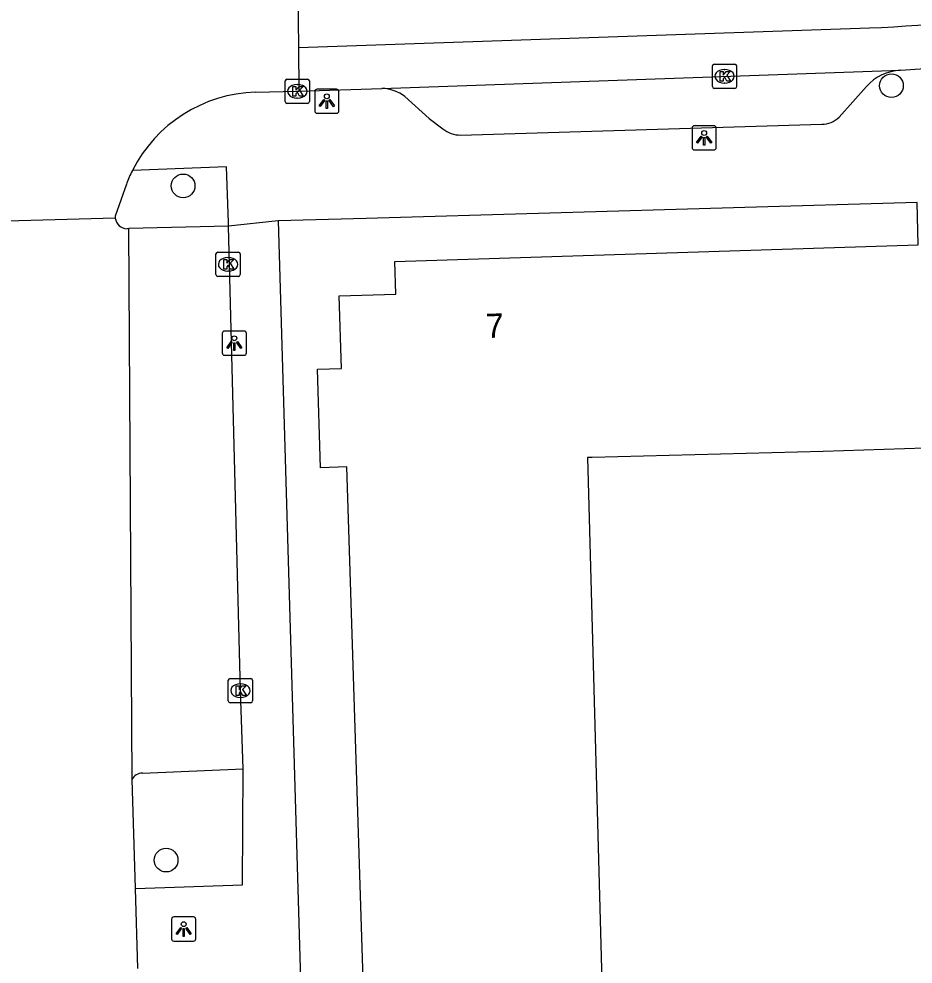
# Model space of a CAD drawing. Extents: x 162250 to 162654, y 380744 to 381605.
# Drawn here: x 162462.41 to 162499.28, y 381169.06 to 381208.05 of the extents above; entities that cross this region are included whole.
import ezdxf

# ---------------------------------------------------------------- set-up
doc = ezdxf.new("R2010")
doc.units = 0
for name, color, linetype in [('IMGEO_Boom', 7, 'Continuous'), ('IMGEO_Kolk', 7, 'Continuous'), ('IMGEO_Lichtpunt', 7, 'Continuous'), ('IMGEO_Pand', 7, 'Continuous'), ('IMGEO_Pand_nummerreeks', 7, 'Continuous'), ('IMGEO_Parkeervlak_open', 7, 'Continuous'), ('IMGEO_Rijbaan_lokaal_gesloten', 7, 'Continuous'), ('IMGEO_Voetpad_open', 7, 'Continuous'), ('IMGEO_Woonerf_open', 7, 'Continuous')]:
    doc.layers.add(name, color=color, linetype=linetype)

msp = doc.modelspace()

# ---------------------------------------------------------------- linework, layer by layer
at = {"layer": 'IMGEO_Boom'}
for centre in [(162498.385, 381205.295), (162469.18, 381201.161), (162468.48, 381173.35)]:
    msp.add_circle(centre, 0.489, dxfattribs=at)
at = {"layer": 'IMGEO_Kolk'}
for p, q in [((162491.003, 381205.258), (162491.003, 381206.11)), ((162491.078, 381206.184), (162491.93, 381206.184)), ((162492.004, 381206.11), (162492.004, 381205.258)), ((162491.491, 381205.964), (162491.516, 381205.964)), ((162473.389, 381204.639), (162473.389, 381205.491)), ((162473.464, 381205.565), (162474.316, 381205.565)), ((162473.877, 381205.345), (162473.902, 381205.345)), ((162474.39, 381205.491), (162474.39, 381204.639)), ((162491.514, 381205.404), (162491.489, 381205.404)), ((162491.93, 381205.184), (162491.078, 381205.184)), ((162474.316, 381204.565), (162473.464, 381204.565)), ((162473.9, 381204.785), (162473.875, 381204.785)), ((162470.534, 381197.501), (162470.534, 381198.353)), ((162470.609, 381198.427), (162471.461, 381198.427)), ((162471.535, 381198.353), (162471.535, 381197.501)), ((162471.022, 381198.207), (162471.047, 381198.207)), ((162471.045, 381197.647), (162471.02, 381197.647)), ((162471.461, 381197.427), (162470.609, 381197.427)), ((162471.044, 381179.916), (162471.044, 381180.768)), ((162471.119, 381180.842), (162471.971, 381180.842)), ((162472.045, 381180.768), (162472.045, 381179.916)), ((162471.532, 381180.622), (162471.557, 381180.622)), ((162471.555, 381180.062), (162471.53, 381180.062)), ((162471.971, 381179.842), (162471.119, 381179.842))]:
    msp.add_line(p, q, dxfattribs=at)
for points in [[(162491.003, 381205.258), (162491.003, 381206.11)], [(162491.078, 381206.184), (162491.93, 381206.184)], [(162492.004, 381206.11), (162492.004, 381205.258)], [(162491.324, 381205.884), (162491.447, 381205.884), (162491.447, 381205.733), (162491.577, 381205.884), (162491.741, 381205.884), (162491.595, 381205.733), (162491.748, 381205.484), (162491.596, 381205.484), (162491.511, 381205.648), (162491.447, 381205.581), (162491.447, 381205.484), (162491.324, 381205.484), (162491.324, 381205.884)], [(162473.389, 381204.639), (162473.389, 381205.491)], [(162473.464, 381205.565), (162474.316, 381205.565)], [(162474.39, 381205.491), (162474.39, 381204.639)], [(162473.71, 381205.265), (162473.833, 381205.265), (162473.833, 381205.114), (162473.963, 381205.265), (162474.127, 381205.265), (162473.981, 381205.114), (162474.134, 381204.865), (162473.982, 381204.865), (162473.897, 381205.029), (162473.833, 381204.962), (162473.833, 381204.865), (162473.71, 381204.865), (162473.71, 381205.265)], [(162491.93, 381205.184), (162491.078, 381205.184)], [(162474.316, 381204.565), (162473.464, 381204.565)], [(162470.534, 381197.501), (162470.534, 381198.353)], [(162470.609, 381198.427), (162471.461, 381198.427)], [(162471.535, 381198.353), (162471.535, 381197.501)], [(162470.855, 381198.127), (162470.978, 381198.127), (162470.978, 381197.976), (162471.108, 381198.127), (162471.272, 381198.127), (162471.126, 381197.976), (162471.279, 381197.727), (162471.127, 381197.727), (162471.042, 381197.891), (162470.978, 381197.824), (162470.978, 381197.727), (162470.855, 381197.727), (162470.855, 381198.127)], [(162471.461, 381197.427), (162470.609, 381197.427)], [(162471.044, 381179.916), (162471.044, 381180.768)], [(162471.119, 381180.842), (162471.971, 381180.842)], [(162472.045, 381180.768), (162472.045, 381179.916)], [(162471.365, 381180.542), (162471.488, 381180.542), (162471.488, 381180.391), (162471.618, 381180.542), (162471.782, 381180.542), (162471.636, 381180.391), (162471.789, 381180.142), (162471.637, 381180.142), (162471.552, 381180.306), (162471.488, 381180.239), (162471.488, 381180.142), (162471.365, 381180.142), (162471.365, 381180.542)], [(162471.971, 381179.842), (162471.119, 381179.842)]]:
    msp.add_lwpolyline(points, dxfattribs=at)
for centre, start, end in [((162491.08, 381206.108), 91.552, 178.448), ((162491.08, 381206.108), 91.552, 178.448), ((162491.928, 381206.108), 1.552, 88.448), ((162491.928, 381206.108), 1.552, 88.448), ((162473.466, 381205.489), 91.552, 178.448), ((162473.466, 381205.489), 91.552, 178.448), ((162474.314, 381205.489), 1.552, 88.448), ((162474.314, 381205.489), 1.552, 88.448), ((162491.08, 381205.26), 181.552, 268.448), ((162491.08, 381205.26), 181.552, 268.448), ((162491.928, 381205.26), 271.552, 358.448), ((162491.928, 381205.26), 271.552, 358.448), ((162473.466, 381204.641), 181.552, 268.448), ((162473.466, 381204.641), 181.552, 268.448), ((162474.314, 381204.641), 271.552, 358.448), ((162474.314, 381204.641), 271.552, 358.448), ((162470.611, 381198.351), 91.552, 178.448), ((162470.611, 381198.351), 91.552, 178.448), ((162471.459, 381198.351), 1.552, 88.448), ((162471.459, 381198.351), 1.552, 88.448), ((162470.611, 381197.503), 181.552, 268.448), ((162470.611, 381197.503), 181.552, 268.448), ((162471.459, 381197.503), 271.552, 358.448), ((162471.459, 381197.503), 271.552, 358.448), ((162471.121, 381180.766), 91.552, 178.448), ((162471.121, 381180.766), 91.552, 178.448), ((162471.969, 381180.766), 1.552, 88.448), ((162471.969, 381180.766), 1.552, 88.448), ((162471.121, 381179.918), 181.552, 268.448), ((162471.121, 381179.918), 181.552, 268.448), ((162471.969, 381179.918), 271.552, 358.448), ((162471.969, 381179.918), 271.552, 358.448)]:
    msp.add_arc(centre, 0.0765, start, end, dxfattribs=at)
for centre, major_axis, ratio, start_param, end_param in [((162491.49, 381205.684), (-0.387, 0.002), 0.722429, 4.712389, 7.853982), ((162491.515, 381205.684), (-0.39, 0.002), 0.717154, 1.570796, 4.712389), ((162473.876, 381205.065), (-0.387, 0.002), 0.722429, 4.712389, 7.853982), ((162473.901, 381205.065), (-0.39, 0.002), 0.717154, 1.570796, 4.712389), ((162471.021, 381197.927), (-0.387, 0.002), 0.722429, 4.712389, 7.853982), ((162471.046, 381197.927), (-0.39, 0.002), 0.717154, 1.570796, 4.712389), ((162471.531, 381180.342), (-0.387, 0.002), 0.722429, 4.712389, 7.853982), ((162471.556, 381180.342), (-0.39, 0.002), 0.717154, 1.570796, 4.712389)]:
    msp.add_ellipse(centre, major_axis=major_axis, ratio=ratio, start_param=start_param, end_param=end_param, dxfattribs=at)
at = {"layer": 'IMGEO_Lichtpunt'}
for p, q in [((162474.61, 381205.057), (162474.61, 381204.25)), ((162474.61, 381205.057), (162474.61, 381204.25)), ((162475.512, 381205.152), (162474.704, 381205.152)), ((162475.512, 381205.152), (162474.704, 381205.152)), ((162475.606, 381204.25), (162475.606, 381205.057)), ((162475.606, 381204.25), (162475.606, 381205.057)), ((162474.704, 381204.156), (162475.512, 381204.156)), ((162474.704, 381204.156), (162475.512, 381204.156)), ((162490.166, 381203.546), (162490.166, 381202.739)), ((162490.166, 381203.546), (162490.166, 381202.739)), ((162491.068, 381203.641), (162490.26, 381203.641)), ((162491.068, 381203.641), (162490.26, 381203.641)), ((162491.162, 381202.739), (162491.162, 381203.546)), ((162491.162, 381202.739), (162491.162, 381203.546)), ((162490.26, 381202.645), (162491.068, 381202.645)), ((162490.26, 381202.645), (162491.068, 381202.645)), ((162471.696, 381195.174), (162470.888, 381195.174)), ((162471.696, 381195.174), (162470.888, 381195.174)), ((162470.794, 381195.079), (162470.794, 381194.272)), ((162470.794, 381195.079), (162470.794, 381194.272)), ((162471.79, 381194.272), (162471.79, 381195.079)), ((162471.79, 381194.272), (162471.79, 381195.079)), ((162470.888, 381194.178), (162471.696, 381194.178)), ((162470.888, 381194.178), (162471.696, 381194.178)), ((162469.609, 381171.007), (162468.801, 381171.007)), ((162469.609, 381171.007), (162468.801, 381171.007)), ((162468.707, 381170.912), (162468.707, 381170.105)), ((162468.707, 381170.912), (162468.707, 381170.105)), ((162469.703, 381170.105), (162469.703, 381170.912)), ((162469.703, 381170.105), (162469.703, 381170.912)), ((162468.801, 381170.011), (162469.609, 381170.011)), ((162468.801, 381170.011), (162469.609, 381170.011))]:
    msp.add_line(p, q, dxfattribs=at)
for points in [[(162474.984, 381204.721), (162475.023, 381204.693), (162474.835, 381204.431), (162474.797, 381204.458), (162474.984, 381204.721)], [(162475.086, 381204.673), (162475.133, 381204.673), (162475.133, 381204.351), (162475.086, 381204.351), (162475.086, 381204.673)], [(162475.196, 381204.693), (162475.234, 381204.72), (162475.421, 381204.458), (162475.382, 381204.43), (162475.196, 381204.693)], [(162490.54, 381203.21), (162490.579, 381203.182), (162490.391, 381202.92), (162490.353, 381202.947), (162490.54, 381203.21)], [(162490.642, 381203.162), (162490.689, 381203.162), (162490.689, 381202.84), (162490.642, 381202.84), (162490.642, 381203.162)], [(162490.752, 381203.182), (162490.79, 381203.209), (162490.977, 381202.947), (162490.938, 381202.919), (162490.752, 381203.182)], [(162471.168, 381194.743), (162471.207, 381194.715), (162471.019, 381194.453), (162470.981, 381194.48), (162471.168, 381194.743)], [(162471.38, 381194.715), (162471.418, 381194.742), (162471.605, 381194.48), (162471.566, 381194.452), (162471.38, 381194.715)], [(162471.27, 381194.695), (162471.317, 381194.695), (162471.317, 381194.373), (162471.27, 381194.373), (162471.27, 381194.695)], [(162469.081, 381170.576), (162469.12, 381170.548), (162468.932, 381170.286), (162468.894, 381170.313), (162469.081, 381170.576)], [(162469.293, 381170.548), (162469.331, 381170.575), (162469.518, 381170.313), (162469.479, 381170.285), (162469.293, 381170.548)], [(162469.183, 381170.528), (162469.23, 381170.528), (162469.23, 381170.206), (162469.183, 381170.206), (162469.183, 381170.528)]]:
    msp.add_lwpolyline(points, dxfattribs=at)
for centre in [(162475.109, 381204.855), (162490.665, 381203.344), (162471.293, 381194.877), (162469.206, 381170.71)]:
    msp.add_circle(centre, 0.0994, dxfattribs=at)
for centre, start, end in [((162474.704, 381205.057), 90, 180), ((162474.704, 381205.057), 90, 180), ((162475.512, 381205.057), 0, 90), ((162475.512, 381205.057), 0, 90), ((162474.704, 381204.25), 180, 270), ((162474.704, 381204.25), 180, 270), ((162475.512, 381204.25), 270, 0), ((162475.512, 381204.25), 270, 360), ((162490.26, 381203.546), 90, 180), ((162490.26, 381203.546), 90, 180), ((162491.068, 381203.546), 0, 90), ((162491.068, 381203.546), 0, 90), ((162490.26, 381202.739), 180, 270), ((162490.26, 381202.739), 180, 270), ((162491.068, 381202.739), 270, 0), ((162491.068, 381202.739), 270, 360), ((162470.888, 381195.079), 90, 180), ((162470.888, 381195.079), 90, 180), ((162471.696, 381195.079), 0, 90), ((162471.696, 381195.079), 0, 90), ((162470.888, 381194.272), 180, 270), ((162470.888, 381194.272), 180, 270), ((162471.696, 381194.272), 270, 0), ((162471.696, 381194.272), 270, 360), ((162468.801, 381170.912), 90, 180), ((162468.801, 381170.912), 90, 180), ((162469.609, 381170.912), 0, 90), ((162469.609, 381170.912), 0, 90), ((162468.801, 381170.105), 180, 270), ((162468.801, 381170.105), 180, 270), ((162469.609, 381170.105), 270, 0), ((162469.609, 381170.105), 270, 360)]:
    msp.add_arc(centre, 0.0946, start, end, dxfattribs=at)
at = {"layer": 'IMGEO_Pand'}
for points in [[(162476.919, 381158.682), (162476.69, 381165.87), (162475.807, 381165.842), (162475.725, 381168.406), (162476.609, 381168.434), (162475.937, 381189.568), (162474.845, 381189.534), (162474.716, 381193.601), (162475.707, 381193.632), (162475.612, 381196.626), (162477.948, 381196.7), (162477.905, 381198.046), (162499.491, 381198.733)], [(162499.758, 381190.345), (162495.568, 381190.211), (162486.051, 381189.962), (162485.85, 381189.955), (162486.547, 381164.836), (162486.591, 381163.246), (162490.367, 381163.38), (162491.387, 381162.494), (162491.431, 381161.107), (162491.494, 381159.132)]]:
    msp.add_lwpolyline(points, dxfattribs=at)
at = {"layer": 'IMGEO_Parkeervlak_open'}
for points in [[(162471.055, 381199.506), (162466.946, 381199.399)], [(162467.074, 381176.672), (162466.946, 381199.399)], [(162467.501, 381176.942), (162471.654, 381177.114)]]:
    msp.add_lwpolyline(points, dxfattribs=at)
msp.add_arc((162467.51, 381176.456), 0.486, 91.0106, 153.6013, dxfattribs=at)
at = {"layer": 'IMGEO_Rijbaan_lokaal_gesloten'}
for points in [[(162473.89, 381211.391), (162473.934, 381206.871)], [(162473.934, 381206.871), (162497.476, 381207.679)], [(162473.934, 381206.871), (162473.952, 381205.067)], [(162477.378, 381205.183), (162498.759, 381205.931)], [(162498.759, 381205.931), (162499.773, 381206.001), (162500, 381206.014), (162500.188, 381206.025)], [(162472.17, 381205.029), (162473.89, 381205.065), (162473.952, 381205.067)], [(162473.952, 381205.067), (162477.378, 381205.183)], [(162466.842, 381201.24), (162466.385, 381199.92), (162466.386, 381199.836)], [(162466.386, 381199.836), (162460.908, 381199.684)]]:
    msp.add_lwpolyline(points, dxfattribs=at)
for centre, radius, start, end in [((162494.819, 381271.411), 63.788, 272.38761, 286.7903), ((162472.358, 381199.124), 5.908, 91.825, 153.0897), ((162472.538, 381199.043), 6.105, 153.1708, 158.9043)]:
    msp.add_arc(centre, radius, start, end, dxfattribs=at)
at = {"layer": 'IMGEO_Voetpad_open'}
for points in [[(162496.224, 381204), (162497.356, 381205.262)], [(162478.329, 381204.843), (162479.326, 381203.941), (162479.891, 381203.513)], [(162480.617, 381203.26), (162495.509, 381203.712)], [(162471.055, 381199.506), (162471.051, 381199.653), (162470.964, 381201.952), (162467.09, 381201.798)], [(162499.491, 381198.733), (162499.446, 381200.478), (162476.73, 381199.814), (162473.106, 381199.726)], [(162473.106, 381199.726), (162471.055, 381199.506)], [(162471.654, 381177.114), (162471.544, 381180.342), (162471.055, 381199.506)], [(162473.106, 381199.726), (162474.836, 381140.858)], [(162467.222, 381172.184), (162471.629, 381172.329), (162471.654, 381177.114)], [(162467.315, 381168.874), (162467.222, 381172.184)]]:
    msp.add_lwpolyline(points, dxfattribs=at)
for centre, radius, start, end in [((162498.86, 381203.913), 2.021, 92.8724, 138.1145), ((162477.305, 381203.478), 1.707, 53.12, 87.5342), ((162495.543, 381204.659), 0.948, 267.948, 315.9309), ((162480.605, 381204.393), 1.133, 230.9548, 270.6199)]:
    msp.add_arc(centre, radius, start, end, dxfattribs=at)
at = {"layer": 'IMGEO_Woonerf_open'}
for points in [[(162466.946, 381199.399), (162466.875, 381199.397)], [(162467.222, 381172.184), (162467.074, 381176.672)]]:
    msp.add_lwpolyline(points, dxfattribs=at)
msp.add_arc((162466.871, 381199.884), 0.488, 185.7083, 270.4598, dxfattribs=at)

# ---------------------------------------------------------------- texts
at = {"layer": 'IMGEO_Pand_nummerreeks'}
msp.add_text('7', height=1, rotation=1.8229, dxfattribs=at).set_placement((162481.674, 381194.885))

doc.saveas('drawing.dxf')
